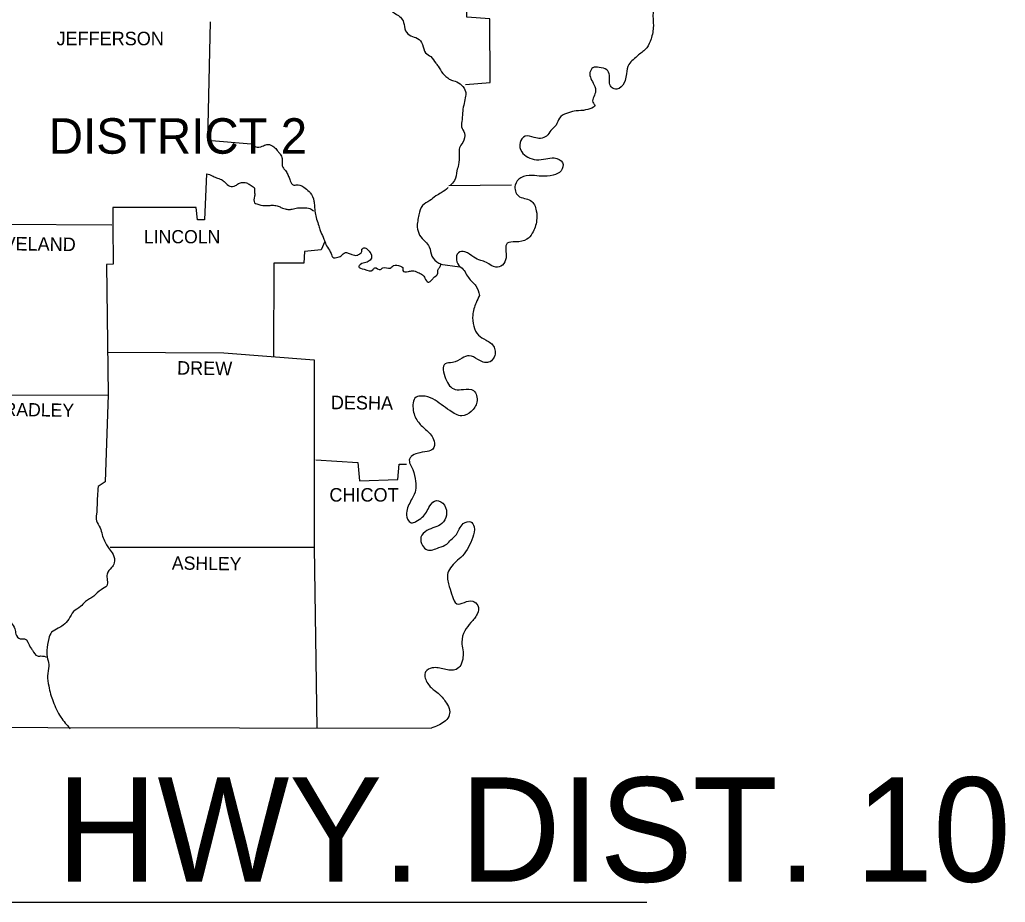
# Model space of a CAD drawing. Extents: x 1334737.7 to 1334827.2, y 402732.3 to 402753.5.
# Drawn here: x 1334823.697 to 1334827.248, y 402746.797 to 402749.977 of the extents above; entities that cross this region are included whole.
import ezdxf

# ---------------------------------------------------------------- set-up
doc = ezdxf.new("R2010")
doc.units = 0
doc.layers.add('Default', color=7, linetype='Continuous')

msp = doc.modelspace()

# ---------------------------------------------------------------- linework, layer by layer
at = {"layer": 'Default'}
for p, q in [((1334825.2428, 402749.3795), (1334825.469, 402749.3826)), ((1334825.2119, 402749.0967), (1334825.2829, 402749.0874)), ((1334820.8432, 402746.7974), (1334825.957, 402746.7974))]:
    msp.add_line(p, q, dxfattribs=at)
for points in [[(1334825.3035, 402749.7445), (1334825.3919, 402749.7507), (1334825.3909, 402749.98), (1334825.3086, 402749.9862), (1334825.3127, 402750.4345), (1334825.2418, 402750.4448), (1334825.2387, 402750.7471), (1334826.2042, 402750.7543)], [(1334824.3831, 402749.9697), (1334824.3739, 402749.544), (1334824.5312, 402749.5306)], [(1334824.3708, 402749.4227), (1334824.3636, 402749.2561), (1334824.3379, 402749.2561), (1334824.3328, 402749.3003), (1334824.0325, 402749.3003), (1334824.0325, 402749.2365)], [(1334823.6294, 402749.2407), (1334824.0294, 402749.2386)], [(1334824.0325, 402749.2386), (1334824.0335, 402749.0967), (1334824.0099, 402749.0957), (1334824.016, 402748.6257)], [(1334824.7965, 402749.1779), (1334824.7831, 402749.1481), (1334824.7235, 402749.1419), (1334824.7204, 402749.1008), (1334824.6124, 402749.1008), (1334824.6114, 402748.7635)], [(1334824.013, 402748.78), (1334824.4325, 402748.7769), (1334824.7585, 402748.7522)], [(1334824.7585, 402748.7522), (1334824.7585, 402748.0756), (1334824.7677, 402747.4247)], [(1334823.505, 402748.6247), (1334824.016, 402748.6257)], [(1334824.016, 402748.6257), (1334824.0047, 402748.3121), (1334823.98, 402748.2957)], [(1334824.7636, 402748.3913), (1334824.9158, 402748.382), (1334824.922, 402748.3162), (1334825.0598, 402748.3203), (1334825.0649, 402748.3759), (1334825.0906, 402748.3759)], [(1334821.033, 402748.3471), (1334821.035, 402747.4319), (1334825.1801, 402747.4247)], [(1334824.0232, 402748.0766), (1334824.7585, 402748.0766)]]:
    msp.add_lwpolyline(points, dxfattribs=at)
for points in [[(1334826.1323, 402750.4797), (1334826.1065, 402750.4479), (1334826.0685, 402750.4674), (1334826.0685, 402750.4952), (1334826.0736, 402750.5229), (1334826.0603, 402750.5414), (1334826.0366, 402750.5332), (1334826.0366, 402750.4983), (1334826.0346, 402750.4643), (1334826.0274, 402750.416), (1334826.0428, 402750.4006), (1334826.0798, 402750.3965), (1334826.1055, 402750.3893), (1334826.1209, 402750.3636), (1334826.1199, 402750.3317), (1334826.1076, 402750.3019), (1334826.0901, 402750.2761), (1334826.0613, 402750.2679), (1334826.0387, 402750.2823), (1334826.0294, 402750.3121), (1334826.0191, 402750.3378), (1334826.0006, 402750.3574), (1334825.9801, 402750.3358), (1334825.9749, 402750.2957), (1334825.977, 402750.2618), (1334825.977, 402750.2155), (1334826.0058, 402750.1846), (1334826.0243, 402750.1497), (1334826.0181, 402750.1178), (1334825.9965, 402750.0808), (1334825.9883, 402750.0479), (1334825.979, 402750.0037), (1334825.9801, 402749.9553), (1334825.9718, 402749.908), (1334825.9564, 402749.8761), (1334825.9266, 402749.8504), (1334825.9071, 402749.833), (1334825.8916, 402749.8165), (1334825.8834, 402749.7826), (1334825.8783, 402749.7589), (1334825.8567, 402749.7301), (1334825.8392, 402749.7281), (1334825.8258, 402749.7394), (1334825.8217, 402749.7589), (1334825.8217, 402749.7774), (1334825.8125, 402749.797), (1334825.7847, 402749.8052), (1334825.7621, 402749.8042), (1334825.7518, 402749.7877), (1334825.7662, 402749.7435), (1334825.7713, 402749.7157), (1334825.7641, 402749.6767), (1334825.7682, 402749.6725), (1334825.7281, 402749.6509), (1334825.6952, 402749.6479), (1334825.6675, 402749.6396), (1334825.6418, 402749.6232), (1334825.6294, 402749.5975), (1334825.6109, 402749.5779), (1334825.5955, 402749.5584), (1334825.5739, 402749.5491)], [(1334824.961, 402750.1157), (1334824.9641, 402750.0695), (1334824.9919, 402750.0623), (1334825.0022, 402750.0499), (1334825.0083, 402750.0242), (1334825.0279, 402750.0129), (1334825.0536, 402749.9975), (1334825.069, 402749.9862), (1334825.0803, 402749.9677), (1334825.0875, 402749.9378), (1334825.106, 402749.9193), (1334825.1307, 402749.9101), (1334825.1482, 402749.8885), (1334825.1595, 402749.8576), (1334825.178, 402749.8443), (1334825.1965, 402749.8206), (1334825.2047, 402749.8103), (1334825.2212, 402749.7836), (1334825.2366, 402749.7702), (1334825.2479, 402749.762), (1334825.2664, 402749.7558), (1334825.2891, 402749.7414), (1334825.3035, 402749.7188), (1334825.3035, 402749.7024), (1334825.2983, 402749.6756), (1334825.2932, 402749.6489), (1334825.2911, 402749.618), (1334825.2891, 402749.5913), (1334825.2993, 402749.5687), (1334825.2932, 402749.5348), (1334825.2819, 402749.5162), (1334825.2808, 402749.4916), (1334825.2777, 402749.4545), (1334825.2726, 402749.433), (1334825.2634, 402749.398), (1334825.2479, 402749.3795)], [(1334825.5739, 402749.5491), (1334825.5502, 402749.5533), (1334825.5184, 402749.5574), (1334825.4999, 402749.5348), (1334825.506, 402749.5018), (1334825.5276, 402749.4823), (1334825.5595, 402749.4731), (1334825.5924, 402749.4761), (1334825.6233, 402749.4792), (1334825.6531, 402749.4628), (1334825.6479, 402749.433), (1334825.6191, 402749.4175), (1334825.577, 402749.4134), (1334825.543, 402749.4165), (1334825.5029, 402749.4083), (1334825.4824, 402749.3815), (1334825.4937, 402749.3425), (1334825.5379, 402749.326), (1334825.5585, 402749.289), (1334825.5595, 402749.254), (1334825.5441, 402749.2078), (1334825.5245, 402749.1862), (1334825.4844, 402749.1769), (1334825.4536, 402749.1718), (1334825.4495, 402749.1193), (1334825.4361, 402749.0936), (1334825.4125, 402749.0854), (1334825.3785, 402749.1029), (1334825.358, 402749.1101), (1334825.3333, 402749.1214), (1334825.3014, 402749.1409), (1334825.2777, 402749.1378), (1334825.2839, 402749.0874), (1334825.287, 402749.0854), (1334825.3137, 402749.0484), (1334825.3405, 402749.0186), (1334825.3538, 402748.9836)], [(1334824.5312, 402749.5306), (1334824.5477, 402749.5193), (1334824.5713, 402749.5214), (1334824.5878, 402749.5276), (1334824.6001, 402749.5265), (1334824.6166, 402749.5162), (1334824.6279, 402749.5029), (1334824.6361, 402749.4926), (1334824.6423, 402749.4772), (1334824.6423, 402749.4617), (1334824.6474, 402749.4422), (1334824.6546, 402749.434), (1334824.6628, 402749.4196), (1334824.669, 402749.4052), (1334824.6721, 402749.397), (1334824.6844, 402749.3815), (1334824.6957, 402749.3826), (1334824.706, 402749.3815), (1334824.7204, 402749.3743), (1334824.74, 402749.3579), (1334824.7441, 402749.3538), (1334824.7574, 402749.324), (1334824.7595, 402749.3065), (1334824.7615, 402749.2818), (1334824.7667, 402749.2592), (1334824.7749, 402749.2345), (1334824.7801, 402749.218), (1334824.7903, 402749.1944), (1334824.7965, 402749.1779), (1334824.8058, 402749.1574), (1334824.8191, 402749.1347), (1334824.8253, 402749.1214), (1334824.8438, 402749.1224)], [(1334824.3708, 402749.4227), (1334824.3903, 402749.4155), (1334824.4058, 402749.4083), (1334824.4243, 402749.4011), (1334824.4366, 402749.3918), (1334824.4541, 402749.3774), (1334824.4747, 402749.3795), (1334824.4891, 402749.3887), (1334824.5034, 402749.3908), (1334824.5148, 402749.3898), (1334824.5271, 402749.3826), (1334824.5415, 402749.3723), (1334824.5436, 402749.3579), (1334824.5436, 402749.3414), (1334824.5436, 402749.3178), (1334824.5518, 402749.3137), (1334824.5795, 402749.3075), (1334824.5991, 402749.3085), (1334824.6166, 402749.3085), (1334824.632, 402749.3044), (1334824.6443, 402749.2982), (1334824.6536, 402749.2962), (1334824.6669, 402749.2931), (1334824.6783, 402749.2952), (1334824.6978, 402749.2993), (1334824.7081, 402749.2993), (1334824.7266, 402749.2993), (1334824.7379, 402749.2982), (1334824.7554, 402749.289)], [(1334825.2407, 402749.3723), (1334825.2161, 402749.3538), (1334825.1965, 402749.3425), (1334825.1749, 402749.326), (1334825.1482, 402749.3075), (1334825.1358, 402749.2746), (1334825.1297, 402749.2294), (1334825.1379, 402749.2016), (1334825.1585, 402749.1779), (1334825.1729, 402749.1594), (1334825.1821, 402749.1255), (1334825.2078, 402749.1008), (1334825.215, 402749.0977)], [(1334824.8438, 402749.1224), (1334824.8582, 402749.1286), (1334824.8685, 402749.1378), (1334824.8808, 402749.1368), (1334824.8942, 402749.1317), (1334824.9117, 402749.1286), (1334824.924, 402749.1347), (1334824.9292, 402749.1399), (1334824.9302, 402749.1502), (1334824.9405, 402749.1553), (1334824.9518, 402749.1481), (1334824.9641, 402749.1296), (1334824.9641, 402749.1183), (1334824.96, 402749.1111), (1334824.9446, 402749.1029), (1334824.925, 402749.0957), (1334824.9189, 402749.0874), (1334824.9384, 402749.0782), (1334824.9693, 402749.0761), (1334824.9765, 402749.0833), (1334824.997, 402749.0772), (1334825.0053, 402749.0833), (1334825.032, 402749.0823), (1334825.0443, 402749.0916), (1334825.069, 402749.0895), (1334825.0772, 402749.0844), (1334825.0772, 402749.0741), (1334825.0978, 402749.07), (1334825.1122, 402749.0731), (1334825.1317, 402749.0669), (1334825.1482, 402749.0587), (1334825.1574, 402749.0463), (1334825.1688, 402749.0319), (1334825.179, 402749.036), (1334825.1873, 402749.0463), (1334825.2037, 402749.0638), (1334825.2037, 402749.0751), (1334825.2089, 402749.0833), (1334825.214, 402749.0946)], [(1334825.3538, 402748.9836), (1334825.3415, 402748.9579), (1334825.3292, 402748.9126), (1334825.3333, 402748.8736), (1334825.3497, 402748.8407), (1334825.3775, 402748.8232), (1334825.4063, 402748.7975), (1334825.4042, 402748.7574), (1334825.3867, 402748.743), (1334825.3477, 402748.7533), (1334825.3168, 402748.7666), (1334825.2911, 402748.7584), (1334825.2562, 402748.7419), (1334825.2304, 402748.7378), (1334825.2315, 402748.6844), (1334825.2664, 402748.6453), (1334825.2963, 402748.6453), (1334825.3322, 402748.6412), (1334825.3446, 402748.6), (1334825.324, 402748.5661), (1334825.2901, 402748.5497), (1334825.2469, 402748.5692), (1334825.2161, 402748.5908), (1334825.1862, 402748.6113), (1334825.1472, 402748.6216), (1334825.1256, 402748.6175), (1334825.1153, 402748.5692), (1334825.1338, 402748.527), (1334825.1636, 402748.4972), (1334825.1903, 402748.4592), (1334825.1862, 402748.4304), (1334825.1657, 402748.4221), (1334825.1297, 402748.4149), (1334825.1081, 402748.4036), (1334825.1019, 402748.3944), (1334825.1132, 402748.3563), (1334825.1235, 402748.3142), (1334825.1235, 402748.2823), (1334825.1112, 402748.2525), (1334825.0916, 402748.2072), (1334825.0947, 402748.1784), (1334825.1081, 402748.1651), (1334825.1245, 402748.1692), (1334825.1472, 402748.1846), (1334825.1626, 402748.2031), (1334825.1749, 402748.2257), (1334825.1986, 402748.2453), (1334825.2274, 402748.2278), (1334825.2346, 402748.1928), (1334825.2181, 402748.162), (1334825.1934, 402748.1486), (1334825.1646, 402748.1373), (1334825.143, 402748.1126), (1334825.1482, 402748.0828), (1334825.1657, 402748.0674), (1334825.2078, 402748.0756), (1334825.2356, 402748.088), (1334825.251, 402748.1034), (1334825.2706, 402748.1229), (1334825.2808, 402748.1424), (1334825.2952, 402748.162)], [(1334823.98, 402748.2957), (1334823.977, 402748.2607), (1334823.9759, 402748.2278), (1334823.9739, 402748.1959), (1334823.9739, 402748.1723), (1334823.9872, 402748.1466), (1334823.9944, 402748.1219), (1334824.0027, 402748.1003), (1334824.0191, 402748.0715), (1334824.0335, 402748.0509), (1334824.0376, 402748.0201), (1334824.0284, 402748.0036), (1334824.0119, 402747.98), (1334824.0109, 402747.9378), (1334823.9903, 402747.9234), (1334823.9646, 402747.9008), (1334823.9492, 402747.8905), (1334823.9338, 402747.8813), (1334823.9163, 402747.8628), (1334823.8916, 402747.8453), (1334823.8741, 402747.8175), (1334823.8536, 402747.7959), (1334823.8361, 402747.7846), (1334823.8124, 402747.7702), (1334823.8022, 402747.7476), (1334823.795, 402747.7054), (1334823.798, 402747.6746), (1334823.8022, 402747.6478), (1334823.797, 402747.6139), (1334823.8022, 402747.5769), (1334823.8083, 402747.5471), (1334823.8176, 402747.5214), (1334823.8299, 402747.4915), (1334823.8453, 402747.4648), (1334823.8793, 402747.4226)], [(1334825.2952, 402748.162), (1334825.322, 402748.1682), (1334825.3343, 402748.1507), (1334825.3292, 402748.1126), (1334825.3137, 402748.0766), (1334825.2921, 402748.0458), (1334825.2685, 402748.0242), (1334825.2387, 402747.9779), (1334825.2448, 402747.9347), (1334825.2562, 402747.8998), (1334825.2716, 402747.873), (1334825.2993, 402747.8782), (1334825.3292, 402747.8823), (1334825.3477, 402747.8669), (1334825.3456, 402747.836), (1334825.323, 402747.8052), (1334825.3014, 402747.7754), (1334825.2901, 402747.7352), (1334825.2942, 402747.7065), (1334825.2942, 402747.6807), (1334825.286, 402747.652), (1334825.2695, 402747.6365), (1334825.2274, 402747.6376), (1334825.1831, 402747.6417), (1334825.1595, 402747.6283), (1334825.1646, 402747.5903), (1334825.1903, 402747.5615), (1334825.2089, 402747.5471), (1334825.2346, 402747.5152), (1334825.2459, 402747.4895), (1334825.2428, 402747.4669), (1334825.2263, 402747.4473), (1334825.1801, 402747.4247)], [(1334822.852, 402748.0345), (1334822.8705, 402748.0468), (1334822.888, 402748.054), (1334822.9045, 402748.0509), (1334822.923, 402748.0478), (1334822.9384, 402748.0509), (1334822.959, 402748.0468), (1334822.9754, 402748.0365), (1334822.9949, 402748.0293), (1334823.0145, 402748.0293), (1334823.0309, 402748.0293), (1334823.0464, 402748.0191), (1334823.0731, 402748.0201), (1334823.0957, 402748.0293), (1334823.1183, 402748.0355), (1334823.1492, 402748.0396), (1334823.1759, 402748.0201), (1334823.1955, 402748.0036), (1334823.2109, 402747.9861), (1334823.2222, 402747.9656), (1334823.2345, 402747.9543), (1334823.2551, 402747.946), (1334823.2705, 402747.943), (1334823.2901, 402747.9378), (1334823.3004, 402747.9327), (1334823.3096, 402747.9111), (1334823.324, 402747.8823), (1334823.3528, 402747.872), (1334823.3878, 402747.8854), (1334823.4155, 402747.8936), (1334823.4361, 402747.8998), (1334823.4484, 402747.9049), (1334823.4597, 402747.9059), (1334823.4567, 402747.908), (1334823.47, 402747.9111), (1334823.4824, 402747.9018), (1334823.4906, 402747.8895), (1334823.504, 402747.872), (1334823.5163, 402747.8556), (1334823.5286, 402747.8504), (1334823.541, 402747.8566), (1334823.5585, 402747.8514), (1334823.5728, 402747.8453), (1334823.5903, 402747.8412), (1334823.6047, 402747.8401), (1334823.6243, 402747.836), (1334823.6387, 402747.8278), (1334823.652, 402747.8196), (1334823.6654, 402747.8052), (1334823.6798, 402747.7825), (1334823.6839, 402747.764), (1334823.6993, 402747.7466), (1334823.7148, 402747.7466), (1334823.7353, 402747.7167), (1334823.7435, 402747.7054), (1334823.761, 402747.6849), (1334823.7734, 402747.6849), (1334823.797, 402747.6807)]]:
    msp.add_spline(points, degree=3, dxfattribs=at)

# ---------------------------------------------------------------- texts
for s, height, p in [('JEFFERSON', 0.04864, (1334823.8299, 402749.8854)), ('DISTRICT 2', 0.12781, (1334823.8022, 402749.4946)), ('LINCOLN', 0.04751, (1334824.1446, 402749.1718)), ('CHICOT', 0.04864, (1334824.813, 402748.2412)), ('ARKANSAS HWY. DIST. 10', 0.376088, (1334820.9517, 402746.8715))]:
    msp.add_text(s, height=height, dxfattribs=at).set_placement(p)
for s, height, rotation, p in [('CLEVELAND', 0.04864, 359.3376, (1334823.5122, 402749.1481)), ('DREW', 0.04863, 359.2258, (1334824.2639, 402748.6988)), ('DESHA', 0.04863, 359.3704, (1334824.8181, 402748.5743)), ('BRADLEY', 0.04749, 359.1449, (1334823.5965, 402748.5507)), ('ASHLEY', 0.04751, 359.2361, (1334824.2453, 402747.9964))]:
    msp.add_text(s, height=height, rotation=rotation, dxfattribs=at).set_placement(p)

doc.saveas('drawing.dxf')
